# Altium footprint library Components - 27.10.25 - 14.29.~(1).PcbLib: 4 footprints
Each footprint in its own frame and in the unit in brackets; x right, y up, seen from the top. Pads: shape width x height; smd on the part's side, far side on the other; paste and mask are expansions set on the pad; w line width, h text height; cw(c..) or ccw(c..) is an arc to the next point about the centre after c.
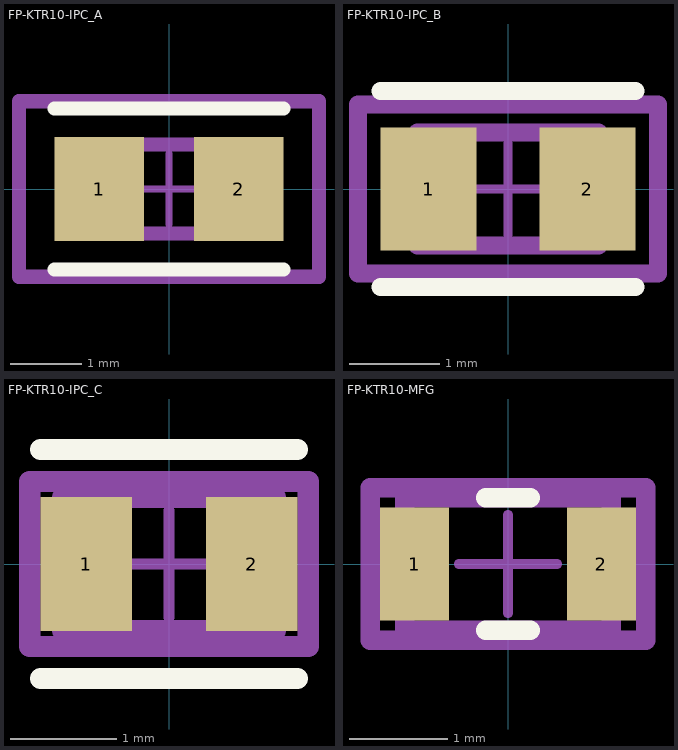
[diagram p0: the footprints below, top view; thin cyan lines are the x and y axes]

## FP-KTR10-IPC_A [mm]
pads (2):
  rect 1.258x1.462 smd paste+0 mask+0: 1(-0.977,0) 2(0.977,0)
Top Overlay:
  lines w0.2: -1.606,-1.131 1.606,-1.131 ; -1.606,1.131 1.606,1.131
Top Assembly:
  lines w0.2: -2.106,-1.231 -2.106,1.231 2.106,1.231 2.106,-1.231 -2.106,-1.231
  text ".Designator" at 0,0.188 h1
Top 3D Body:
  lines w0.2: -1,-0.625 -1,0.625 1,0.625 1,-0.625 -1,-0.625
Top Courtyard:
  lines w0.2: -2.106,-1.231 -2.106,1.231 2.106,1.231 2.106,-1.231 -2.106,-1.231
Top Component Center:
  lines w0.1: -0.5,0 0.5,0 ; 0,-0.5 0,0.5
3D body "Res_Rohm_KTR10EZPJ151_eec.STEP": height 0.25, standoff 0, extent -2.106,-1.231 2.106,1.231

## FP-KTR10-IPC_B [mm]
pads (2):
  rect 1.058x1.362 smd paste+0 mask+0: 1(-0.877,0) 2(0.877,0)
Top Overlay:
  lines w0.2: -1.406,-1.081 1.406,-1.081 ; -1.406,1.081 1.406,1.081
Top Assembly:
  lines w0.2: -1.656,-0.931 1.656,-0.931 1.656,0.931 -1.656,0.931 -1.656,-0.931
  text ".Designator" at 0,0.188 h1
Top 3D Body:
  lines w0.2: -1,-0.625 1,-0.625 1,0.625 -1,0.625 -1,-0.625
Top Courtyard:
  lines w0.2: -1.656,-0.931 1.656,-0.931 1.656,0.931 -1.656,0.931 -1.656,-0.931
Top Component Center:
  lines w0.1: -0.5,0 0.5,0 ; 0,-0.5 0,0.5
3D body "Res_Rohm_KTR10EZPJ151_eec.STEP": height 0.25, standoff 0, extent -1.656,-0.931 1.656,0.931

## FP-KTR10-IPC_C [mm]
pads (2):
  rect 0.858x1.262 smd paste+0 mask+0: 1(-0.777,0) 2(0.777,0)
Top Overlay:
  lines w0.2: -1.206,-1.075 1.206,-1.075 ; -1.206,1.075 1.206,1.075
Top Assembly:
  lines w0.2: -1.306,-0.775 1.306,-0.775 1.306,0.775 -1.306,0.775 -1.306,-0.775
  text ".Designator" at 0,0.188 h1
Top 3D Body:
  lines w0.2: -1,-0.625 1,-0.625 1,0.625 -1,0.625 -1,-0.625
Top Courtyard:
  lines w0.2: -1.306,-0.775 1.306,-0.775 1.306,0.775 -1.306,0.775 -1.306,-0.775
Top Component Center:
  lines w0.1: -0.5,0 0.5,0 ; 0,-0.5 0,0.5
3D body "Res_Rohm_KTR10EZPJ151_eec.STEP": height 0.25, standoff 0, extent -1.306,-0.775 1.306,0.775

## FP-KTR10-MFG [mm]
pads (2):
  rect 0.7x1.15 smd paste+0 mask+0: 1(-0.95,0) 2(0.95,0)
Top Overlay:
  lines w0.2: -0.225,-0.675 0.225,-0.675 ; -0.225,0.675 0.225,0.675
Top Assembly:
  lines w0.2: -1.4,-0.775 1.4,-0.775 1.4,0.775 -1.4,0.775 -1.4,-0.775
  text ".Designator" at 0,0.188 h1
Top 3D Body:
  lines w0.2: -1.05,-0.675 1.05,-0.675 1.05,0.675 -1.05,0.675 -1.05,-0.675
Top Courtyard:
  lines w0.2: -1.4,-0.775 1.4,-0.775 1.4,0.775 -1.4,0.775 -1.4,-0.775
Top Component Center:
  lines w0.1: -0.5,0 0.5,0 ; 0,-0.5 0,0.5
3D body "Res_Rohm_KTR10EZPJ151_eec.STEP": height 0.25, standoff 0, extent -1.4,-0.775 1.4,0.775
